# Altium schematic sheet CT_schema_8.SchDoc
size 391 x 238 mm
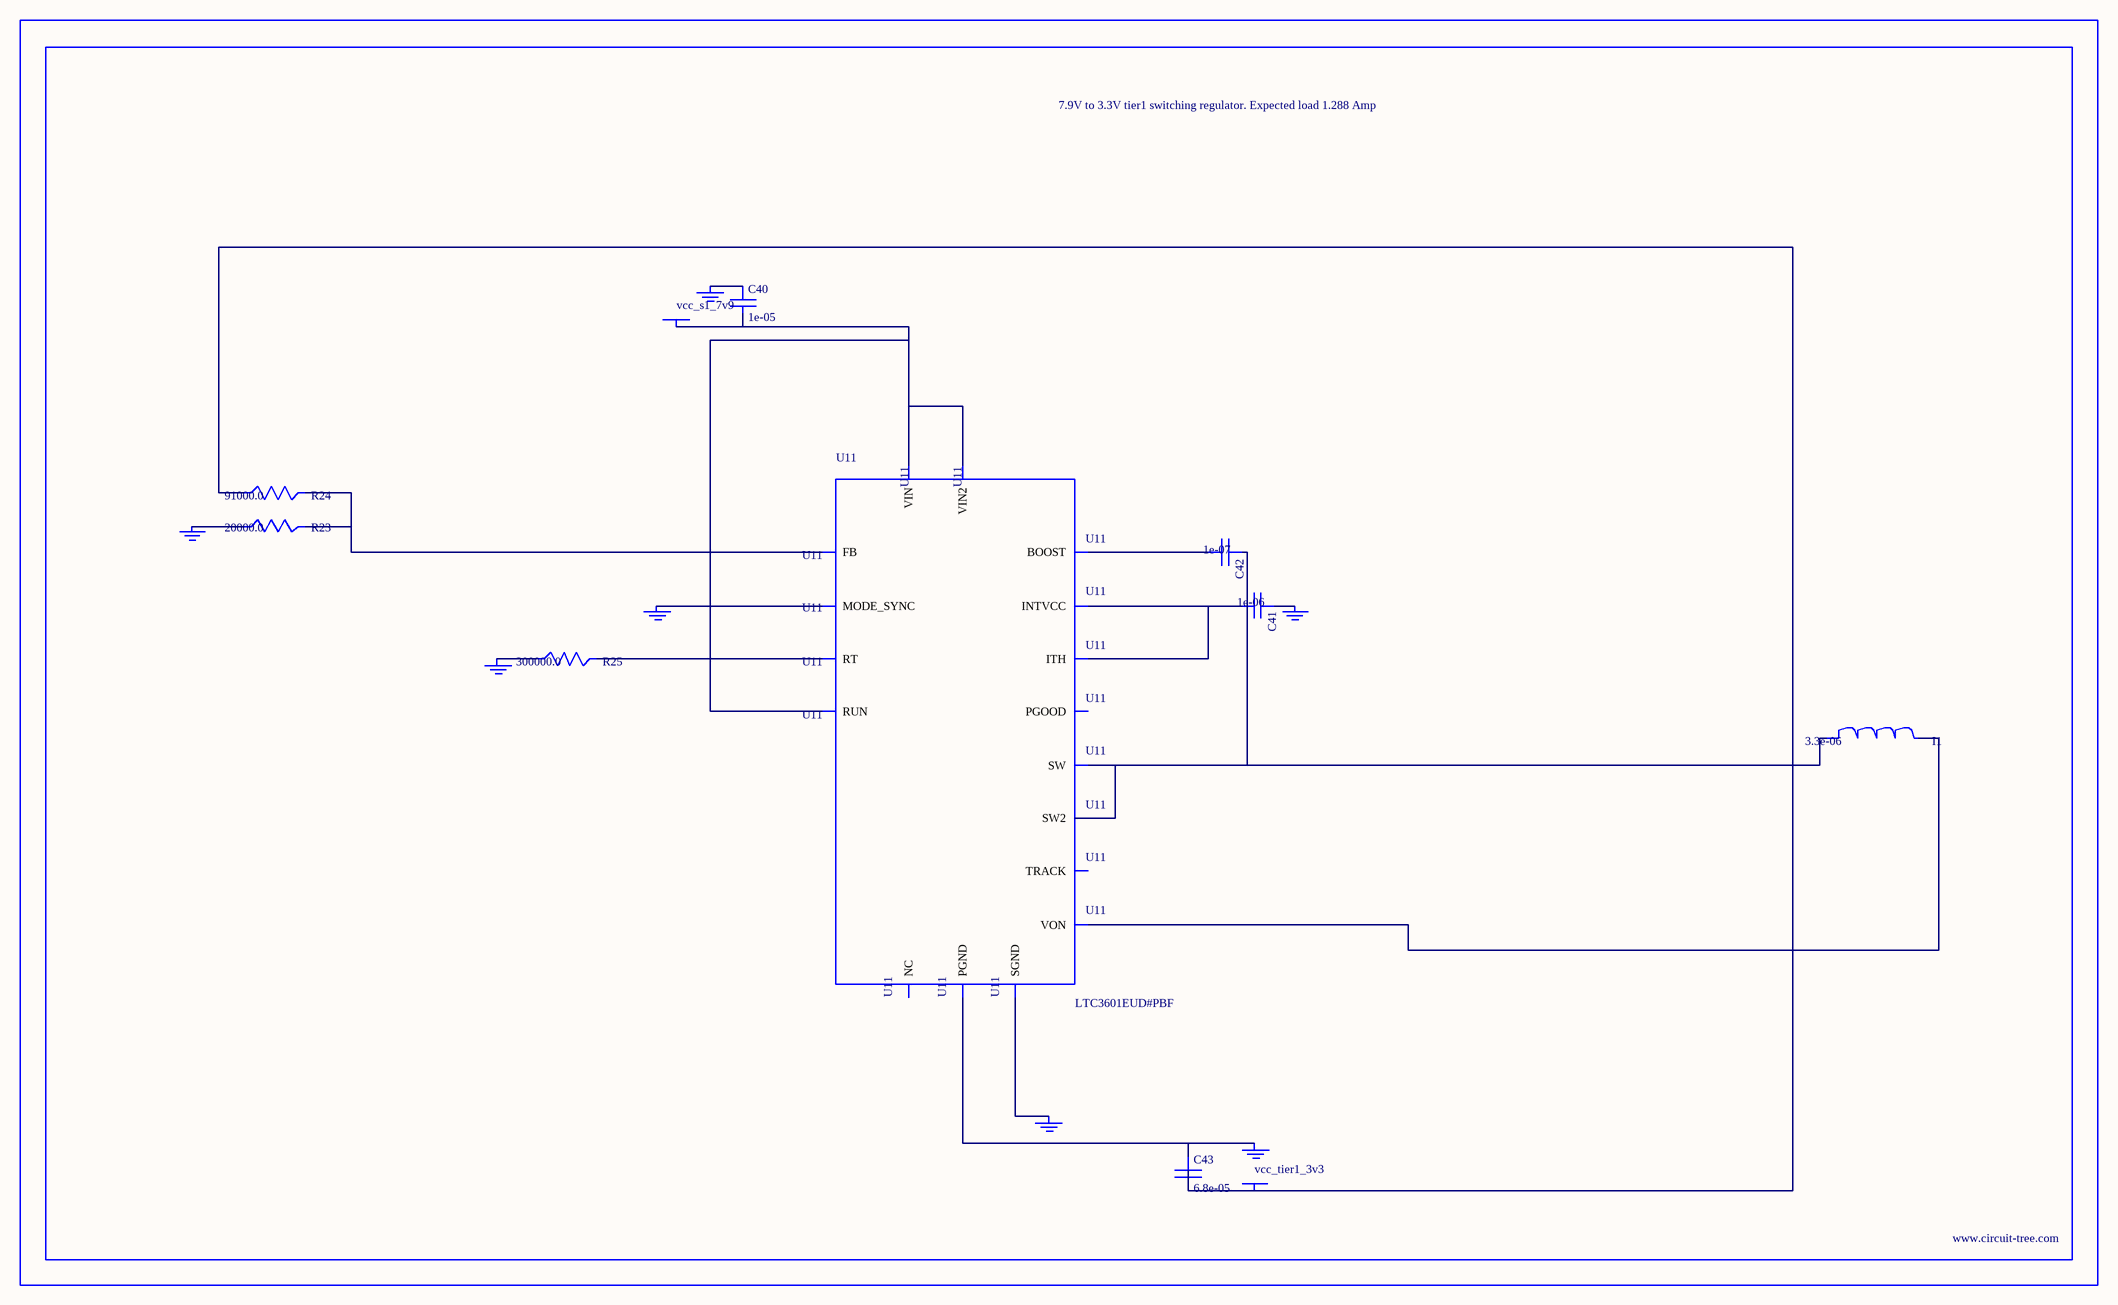
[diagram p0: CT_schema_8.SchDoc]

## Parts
BORDER7  (no value)
C40  1e-05  [C0805]
C41  1e-06  [C0603]
C42  1e-07  [C0402]
C43  6.8e-05  [2220]
GND_INSTANCE_7_0  (no value)
GND_INSTANCE_7_1  (no value)
GND_INSTANCE_7_2  (no value)
GND_INSTANCE_7_3  (no value)
GND_INSTANCE_7_4  (no value)
GND_INSTANCE_7_5  (no value)
GND_INSTANCE_7_6  (no value)
I1  3.3e-06  [WE-HCI_7030/7040/7050]
POWER_INSTANCE_7_0  vcc_s1_7v9
POWER_INSTANCE_7_1  vcc_tier1_3v3
R23  20000.0  [R0603]
R24  91000.0  [R0603]
R25  300000.0  [R0603]
U11  LTC3601EUD#PBF  [QFN-16_EP]

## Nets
NetC40_1: C40.1 GND_INSTANCE_7_5.0(GND)
NetC40_2: C40.2 POWER_INSTANCE_7_0.0(PWR) U11.14(RUN) U11.15(VIN) U11.16(VIN2)
NetC41_1: C41.1 GND_INSTANCE_7_1.0(GND)
NetC41_2: C41.2 U11.7(INTVCC) U11.12(ITH)
NetC42_1: C42.1 I1.1 U11.3(SW) U11.4(SW2)
NetC42_2: C42.2 U11.6(BOOST)
NetC43_1: C43.1 GND_INSTANCE_7_6.0(GND) U11.17(PGND)
NetC43_2: C43.2 I1.2 POWER_INSTANCE_7_1.0(PWR) R24.1 U11.8(VON)
NetGND_INSTANCE_7_0_0: GND_INSTANCE_7_0.0(GND) U11.1(MODE_SYNC)
NetGND_INSTANCE_7_2_0: GND_INSTANCE_7_2.0(GND) U11.9(SGND)
NetGND_INSTANCE_7_3_0: GND_INSTANCE_7_3.0(GND) R25.1
NetGND_INSTANCE_7_4_0: GND_INSTANCE_7_4.0(GND) R23.1
NetR23_2: R23.2 R24.2 U11.11(FB)
NetR25_2: R25.2 U11.10(RT)

Not connected (* = marked no-connect by the designer): U11 2(PGOOD) 5(NC) 13(TRACK)

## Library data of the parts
BORDER7 = BORDER_PAGE7
C40 = C0805C106K8RACTU
C41 = C0603C105K3RACTU
C42 = C0402C104K3RACTU
C43 = C5750X5R1A686M
GND_INSTANCE_7_0-GND_INSTANCE_7_6 = GND
I1 = 744314330
POWER_INSTANCE_7_0 POWER_INSTANCE_7_1 = PWR
R23 = RC0603JR-0720KL
R24 = RC0603JR-0791KL
R25 = RC0603JR-07300KL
